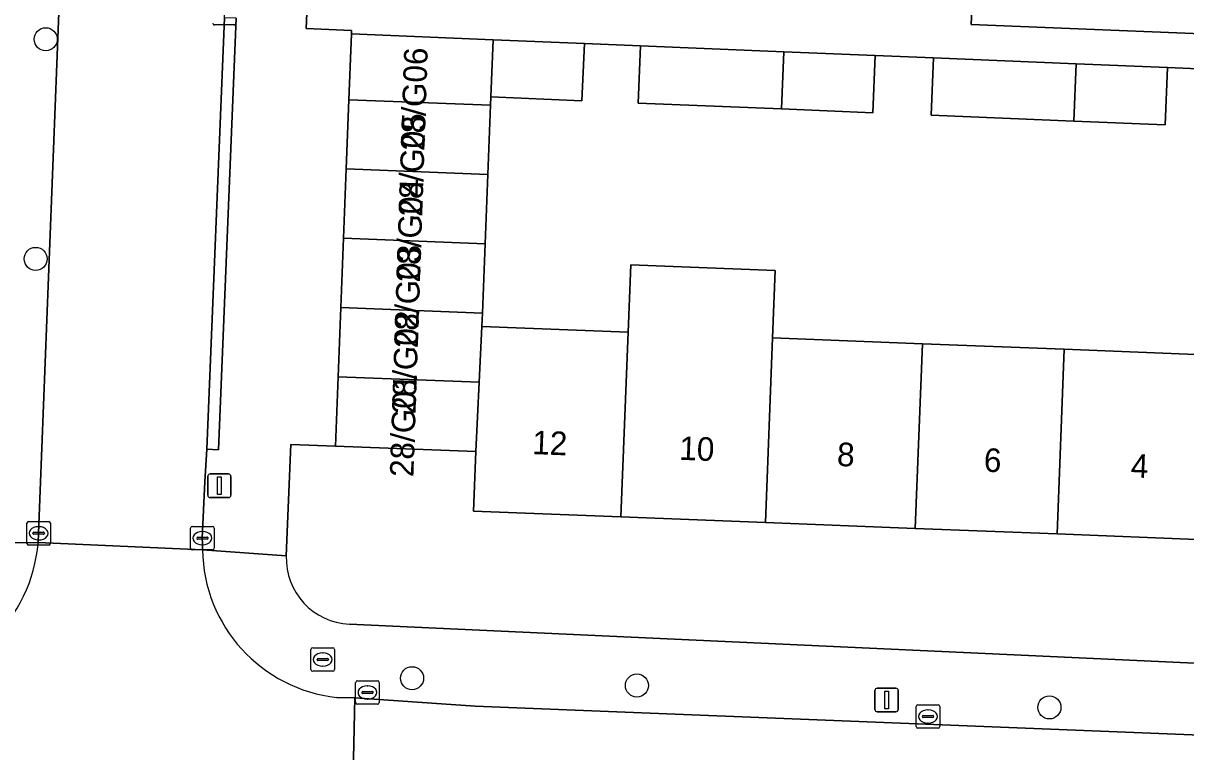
# Model space of a CAD drawing. Extents: x 161354 to 162026, y 386504 to 387460.
# Drawn here: x 161732.92 to 161782.27, y 386817.34 to 386848.27 of the extents above; entities that cross this region are included whole.
import ezdxf

# ---------------------------------------------------------------- set-up
doc = ezdxf.new("R2010")
doc.units = 0
for name, color, linetype in [('IMGEO_Boom', 7, 'Continuous'), ('IMGEO_Brandkraan', 7, 'Continuous'), ('IMGEO_Erf', 7, 'Continuous'), ('IMGEO_Kolk', 7, 'Continuous'), ('IMGEO_Lichtmast', 7, 'Continuous'), ('IMGEO_Pand', 7, 'Continuous'), ('IMGEO_Pand_nummerreeks', 7, 'Continuous'), ('IMGEO_Rijbaan_lokaal_open', 7, 'Continuous'), ('IMGEO_Voetpad_open', 7, 'Continuous')]:
    doc.layers.add(name, color=color, linetype=linetype)

msp = doc.modelspace()

# ---------------------------------------------------------------- linework, layer by layer
at = {"layer": 'IMGEO_Boom'}
for centre in [(161733.871, 386847.589), (161733.442, 386838.265), (161749.424, 386820.465), (161758.968, 386820.154), (161776.484, 386819.225)]:
    msp.add_circle(centre, 0.489, dxfattribs=at)
at = {"layer": 'IMGEO_Brandkraan'}
for p, q in [((161745.131, 386820.831), (161745.131, 386821.683)), ((161745.206, 386821.757), (161746.058, 386821.757)), ((161745.619, 386821.537), (161745.644, 386821.537)), ((161746.132, 386821.683), (161746.132, 386820.831)), ((161745.39, 386821.251), (161745.39, 386821.263)), ((161745.828, 386821.214), (161745.43, 386821.214)), ((161745.433, 386821.3), (161745.831, 386821.3)), ((161745.642, 386820.977), (161745.617, 386820.977)), ((161745.874, 386821.263), (161745.874, 386821.251)), ((161746.058, 386820.757), (161745.206, 386820.757))]:
    msp.add_line(p, q, dxfattribs=at)
for points in [[(161745.131, 386820.831), (161745.131, 386821.683)], [(161745.206, 386821.757), (161746.058, 386821.757)], [(161746.132, 386821.683), (161746.132, 386820.831)], [(161746.058, 386820.757), (161745.206, 386820.757)]]:
    msp.add_lwpolyline(points, dxfattribs=at)
for centre, radius, start, end in [((161745.208, 386821.681), 0.0765, 91.552, 178.448), ((161745.208, 386821.681), 0.0765, 91.552, 178.448), ((161746.056, 386821.681), 0.0765, 1.552, 88.448), ((161746.056, 386821.681), 0.0765, 1.552, 88.448), ((161745.208, 386820.833), 0.0765, 181.552, 268.448), ((161745.208, 386820.833), 0.0765, 181.552, 268.448), ((161745.43, 386821.26), 0.0403, 85.8775, 175.7526), ((161745.427, 386821.25), 0.0366, 178.938, 274.7102), ((161745.831, 386821.257), 0.043, 264.8664, 352.4533), ((161745.835, 386821.262), 0.0386, 1.7309, 96.639), ((161746.056, 386820.833), 0.0765, 271.552, 358.448), ((161746.056, 386820.833), 0.0765, 271.552, 358.448)]:
    msp.add_arc(centre, radius, start, end, dxfattribs=at)
for centre, major_axis, ratio, start_param, end_param in [((161745.618, 386821.257), (-0.387, 0.002), 0.722429, 4.712389, 7.853982), ((161745.643, 386821.257), (-0.39, 0.002), 0.717154, 1.570796, 4.712389)]:
    msp.add_ellipse(centre, major_axis=major_axis, ratio=ratio, start_param=start_param, end_param=end_param, dxfattribs=at)
at = {"layer": 'IMGEO_Erf'}
for points in [[(161774.801, 386890.94), (161774.595, 386885.544), (161776.967, 386885.442), (161776.817, 386881.514), (161776.669, 386877.637), (161774.297, 386877.739), (161774.194, 386875.016), (161774.094, 386872.396), (161776.466, 386872.294), (161776.319, 386868.314), (161776.062, 386861.714), (161773.692, 386861.815), (161773.578, 386858.814), (161775.948, 386858.712), (161775.812, 386855.113), (161775.658, 386851.101), (161773.288, 386851.191), (161773.167, 386848.216), (161787.125, 386847.647)], [(161786.367, 386846.182), (161781.498, 386846.383), (161781.398, 386843.955), (161777.521, 386844.115), (161771.466, 386844.366), (161771.567, 386846.793), (161769.088, 386846.896), (161768.987, 386844.468), (161765.111, 386844.628), (161759.028, 386844.879), (161759.129, 386847.307), (161756.738, 386847.406), (161756.638, 386844.978), (161752.769, 386845.138), (161752.753, 386844.787), (161752.638, 386841.847), (161752.523, 386838.906), (161752.408, 386835.966), (161752.386, 386835.39), (161758.598, 386835.148), (161758.71, 386838.01), (161764.843, 386837.77), (161764.731, 386834.909), (161771.093, 386834.662), (161777.113, 386834.427), (161783.392, 386834.183)], [(161776.807, 386826.59), (161770.787, 386826.824), (161764.425, 386827.072), (161758.292, 386827.311), (161752.029, 386827.555), (161752.128, 386830.087), (161746.171, 386830.319), (161744.271, 386830.386), (161744.084, 386825.658)], [(161796.626, 386823.094), (161796.939, 386828.203), (161795.513, 386828.34), (161795.296, 386828.361), (161789.554, 386828.585), (161789.457, 386826.097), (161783.086, 386826.345), (161776.807, 386826.59)], [(161746.765, 386822.756), (161793.994, 386820.574)]]:
    msp.add_lwpolyline(points, dxfattribs=at)
msp.add_arc((161746.888, 386825.559), 2.805, 177.9708, 267.4955, dxfattribs=at)
at = {"layer": 'IMGEO_Kolk'}
for p, q in [((161741.888, 386848.193), (161741.036, 386848.193)), ((161733.069, 386826.189), (161733.069, 386827.041)), ((161733.144, 386827.115), (161733.996, 386827.115)), ((161733.557, 386826.895), (161733.582, 386826.895)), ((161734.07, 386827.041), (161734.07, 386826.189)), ((161740.023, 386825.982), (161740.023, 386826.834)), ((161740.098, 386826.908), (161740.95, 386826.908)), ((161741.024, 386826.834), (161741.024, 386825.982)), ((161733.328, 386826.609), (161733.328, 386826.621)), ((161733.766, 386826.572), (161733.368, 386826.572)), ((161733.371, 386826.658), (161733.769, 386826.658)), ((161733.58, 386826.335), (161733.555, 386826.335)), ((161733.812, 386826.621), (161733.812, 386826.609)), ((161740.282, 386826.402), (161740.282, 386826.414)), ((161740.72, 386826.365), (161740.322, 386826.365)), ((161740.325, 386826.451), (161740.723, 386826.451)), ((161740.511, 386826.688), (161740.536, 386826.688)), ((161740.766, 386826.414), (161740.766, 386826.402)), ((161733.996, 386826.115), (161733.144, 386826.115)), ((161740.95, 386825.908), (161740.098, 386825.908)), ((161740.534, 386826.128), (161740.509, 386826.128)), ((161747.104, 386820.358), (161747.956, 386820.358)), ((161747.029, 386819.432), (161747.029, 386820.284)), ((161747.288, 386819.852), (161747.288, 386819.864)), ((161747.331, 386819.901), (161747.729, 386819.901)), ((161747.517, 386820.138), (161747.542, 386820.138)), ((161747.772, 386819.864), (161747.772, 386819.852)), ((161748.03, 386820.284), (161748.03, 386819.432)), ((161747.956, 386819.358), (161747.104, 386819.358)), ((161747.726, 386819.815), (161747.328, 386819.815)), ((161747.54, 386819.578), (161747.515, 386819.578)), ((161770.903, 386819.338), (161771.755, 386819.338)), ((161770.828, 386818.412), (161770.828, 386819.264)), ((161771.087, 386818.832), (161771.087, 386818.844)), ((161771.13, 386818.881), (161771.528, 386818.881)), ((161771.316, 386819.118), (161771.341, 386819.118)), ((161771.571, 386818.844), (161771.571, 386818.832)), ((161771.829, 386819.264), (161771.829, 386818.412)), ((161771.525, 386818.795), (161771.127, 386818.795)), ((161771.339, 386818.558), (161771.314, 386818.558)), ((161771.755, 386818.338), (161770.903, 386818.338))]:
    msp.add_line(p, q, dxfattribs=at)
for points in [[(161741.888, 386848.193), (161741.036, 386848.193)], [(161733.069, 386826.189), (161733.069, 386827.041)], [(161733.144, 386827.115), (161733.996, 386827.115)], [(161734.07, 386827.041), (161734.07, 386826.189)], [(161740.023, 386825.982), (161740.023, 386826.834)], [(161740.098, 386826.908), (161740.95, 386826.908)], [(161741.024, 386826.834), (161741.024, 386825.982)], [(161733.996, 386826.115), (161733.144, 386826.115)], [(161740.95, 386825.908), (161740.098, 386825.908)], [(161747.104, 386820.358), (161747.956, 386820.358)], [(161747.029, 386819.432), (161747.029, 386820.284)], [(161748.03, 386820.284), (161748.03, 386819.432)], [(161747.956, 386819.358), (161747.104, 386819.358)], [(161770.903, 386819.338), (161771.755, 386819.338)], [(161770.828, 386818.412), (161770.828, 386819.264)], [(161771.829, 386819.264), (161771.829, 386818.412)], [(161771.755, 386818.338), (161770.903, 386818.338)]]:
    msp.add_lwpolyline(points, dxfattribs=at)
for centre, radius, start, end in [((161741.038, 386848.269), 0.0765, 181.552, 268.448), ((161741.038, 386848.269), 0.0765, 181.552, 268.448), ((161741.886, 386848.269), 0.0765, 271.552, 358.448), ((161741.886, 386848.269), 0.0765, 271.552, 358.448), ((161733.146, 386827.039), 0.0765, 91.552, 178.448), ((161733.146, 386827.039), 0.0765, 91.552, 178.448), ((161733.994, 386827.039), 0.0765, 1.552, 88.448), ((161733.994, 386827.039), 0.0765, 1.552, 88.448), ((161740.1, 386826.832), 0.0765, 91.552, 178.448), ((161740.1, 386826.832), 0.0765, 91.552, 178.448), ((161740.948, 386826.832), 0.0765, 1.552, 88.448), ((161740.948, 386826.832), 0.0765, 1.552, 88.448), ((161733.368, 386826.618), 0.0403, 85.8775, 175.7526), ((161733.365, 386826.608), 0.0366, 178.938, 274.7102), ((161733.769, 386826.615), 0.043, 264.8664, 352.4533), ((161733.773, 386826.62), 0.0386, 1.7309, 96.639), ((161740.322, 386826.411), 0.0403, 85.8775, 175.7526), ((161740.319, 386826.401), 0.0366, 178.938, 274.7102), ((161740.723, 386826.408), 0.043, 264.8664, 352.4533), ((161740.727, 386826.413), 0.0386, 1.7309, 96.639), ((161733.146, 386826.191), 0.0765, 181.552, 268.448), ((161733.146, 386826.191), 0.0765, 181.552, 268.448), ((161733.994, 386826.191), 0.0765, 271.552, 358.448), ((161733.994, 386826.191), 0.0765, 271.552, 358.448), ((161740.1, 386825.984), 0.0765, 181.552, 268.448), ((161740.1, 386825.984), 0.0765, 181.552, 268.448), ((161740.948, 386825.984), 0.0765, 271.552, 358.448), ((161740.948, 386825.984), 0.0765, 271.552, 358.448), ((161747.106, 386820.282), 0.0765, 91.552, 178.448), ((161747.106, 386820.282), 0.0765, 91.552, 178.448), ((161747.954, 386820.282), 0.0765, 1.552, 88.448), ((161747.954, 386820.282), 0.0765, 1.552, 88.448), ((161747.328, 386819.861), 0.0403, 85.8775, 175.7526), ((161747.325, 386819.851), 0.0366, 178.938, 274.7102), ((161747.729, 386819.858), 0.043, 264.8664, 352.4533), ((161747.733, 386819.863), 0.0386, 1.7309, 96.639), ((161747.106, 386819.434), 0.0765, 181.552, 268.448), ((161747.106, 386819.434), 0.0765, 181.552, 268.448), ((161747.954, 386819.434), 0.0765, 271.552, 358.448), ((161747.954, 386819.434), 0.0765, 271.552, 358.448), ((161770.905, 386819.262), 0.0765, 91.552, 178.448), ((161770.905, 386819.262), 0.0765, 91.552, 178.448), ((161771.753, 386819.262), 0.0765, 1.552, 88.448), ((161771.753, 386819.262), 0.0765, 1.552, 88.448), ((161771.127, 386818.841), 0.0403, 85.8775, 175.7526), ((161771.532, 386818.843), 0.0386, 1.7309, 96.639), ((161770.905, 386818.414), 0.0765, 181.552, 268.448), ((161770.905, 386818.414), 0.0765, 181.552, 268.448), ((161771.124, 386818.831), 0.0366, 178.938, 274.7102), ((161771.528, 386818.838), 0.043, 264.8664, 352.4533), ((161771.753, 386818.414), 0.0765, 271.552, 358.448), ((161771.753, 386818.414), 0.0765, 271.552, 358.448)]:
    msp.add_arc(centre, radius, start, end, dxfattribs=at)
for centre, major_axis, ratio, start_param, end_param in [((161733.556, 386826.615), (-0.387, 0.002), 0.722429, 4.712389, 7.853982), ((161733.581, 386826.615), (-0.39, 0.002), 0.717154, 1.570796, 4.712389), ((161740.51, 386826.408), (-0.387, 0.002), 0.722429, 4.712389, 7.853982), ((161740.535, 386826.408), (-0.39, 0.002), 0.717154, 1.570796, 4.712389), ((161747.516, 386819.858), (-0.387, 0.002), 0.722429, 4.712389, 7.853982), ((161747.541, 386819.858), (-0.39, 0.002), 0.717154, 1.570796, 4.712389), ((161771.315, 386818.838), (-0.387, 0.002), 0.722429, 4.712389, 7.853982), ((161771.34, 386818.838), (-0.39, 0.002), 0.717154, 1.570796, 4.712389)]:
    msp.add_ellipse(centre, major_axis=major_axis, ratio=ratio, start_param=start_param, end_param=end_param, dxfattribs=at)
at = {"layer": 'IMGEO_Lichtmast'}
for p, q in [((161740.746, 386828.233), (161740.746, 386829.033)), ((161740.746, 386829.033), (161740.746, 386828.233)), ((161740.846, 386829.133), (161741.636, 386829.133)), ((161741.636, 386829.133), (161740.846, 386829.133)), ((161741.736, 386829.033), (161741.736, 386828.233)), ((161741.736, 386828.233), (161741.736, 386829.033)), ((161741.636, 386828.133), (161740.846, 386828.133)), ((161740.846, 386828.133), (161741.636, 386828.133)), ((161769.077, 386819.141), (161769.077, 386819.941)), ((161769.077, 386819.941), (161769.077, 386819.141)), ((161769.177, 386820.041), (161769.967, 386820.041)), ((161769.967, 386820.041), (161769.177, 386820.041)), ((161770.067, 386819.941), (161770.067, 386819.141)), ((161770.067, 386819.141), (161770.067, 386819.941)), ((161769.967, 386819.041), (161769.177, 386819.041)), ((161769.177, 386819.041), (161769.967, 386819.041))]:
    msp.add_line(p, q, dxfattribs=at)
for points in [[(161741.166, 386829.008), (161741.316, 386829.008), (161741.316, 386828.258), (161741.166, 386828.258), (161741.166, 386829.008)], [(161769.497, 386819.916), (161769.647, 386819.916), (161769.647, 386819.166), (161769.497, 386819.166), (161769.497, 386819.916)]]:
    msp.add_lwpolyline(points, dxfattribs=at)
for centre, start, end in [((161740.846, 386829.033), 90, 180), ((161740.846, 386829.033), 90, 180), ((161741.636, 386829.033), 0, 90), ((161741.636, 386829.033), 360, 90), ((161740.846, 386828.233), 180, 270), ((161740.846, 386828.233), 180, 270), ((161741.636, 386828.233), 270, 0), ((161741.636, 386828.233), 270, 0), ((161769.177, 386819.941), 90, 180), ((161769.177, 386819.941), 90, 180), ((161769.967, 386819.941), 0, 90), ((161769.967, 386819.941), 360, 90), ((161769.177, 386819.141), 180, 270), ((161769.177, 386819.141), 180, 270), ((161769.967, 386819.141), 270, 0), ((161769.967, 386819.141), 270, 0)]:
    msp.add_arc(centre, 0.1, start, end, dxfattribs=at)
at = {"layer": 'IMGEO_Pand'}
for points in [[(161752.862, 386847.566), (161746.853, 386847.815), (161746.744, 386845.022), (161752.753, 386844.787), (161752.769, 386845.138)], [(161756.738, 386847.406), (161752.862, 386847.566), (161752.769, 386845.138), (161756.638, 386844.978)], [(161765.211, 386847.056), (161759.129, 386847.307), (161759.028, 386844.879), (161765.111, 386844.628)], [(161769.088, 386846.896), (161765.211, 386847.056), (161765.111, 386844.628), (161768.987, 386844.468)], [(161777.621, 386846.543), (161771.567, 386846.793), (161771.466, 386844.366), (161777.521, 386844.115)], [(161781.498, 386846.383), (161777.621, 386846.543), (161777.521, 386844.115), (161781.398, 386843.955)], [(161752.638, 386841.847), (161752.753, 386844.787), (161746.744, 386845.022), (161746.63, 386842.081)], [(161746.63, 386842.081), (161746.515, 386839.14), (161752.523, 386838.906), (161752.638, 386841.847)], [(161752.408, 386835.966), (161752.523, 386838.906), (161746.515, 386839.14), (161746.4, 386836.2)], [(161764.731, 386834.909), (161764.843, 386837.77), (161758.71, 386838.01), (161758.598, 386835.148), (161758.292, 386827.311), (161764.425, 386827.072)], [(161746.4, 386836.2), (161746.286, 386833.26), (161752.271, 386833.026), (161752.386, 386835.39), (161752.408, 386835.966)], [(161752.128, 386830.087), (161752.029, 386827.555), (161758.292, 386827.311), (161758.598, 386835.148), (161752.386, 386835.39), (161752.271, 386833.026)], [(161771.093, 386834.662), (161764.731, 386834.909), (161764.425, 386827.072), (161770.787, 386826.824)], [(161770.787, 386826.824), (161776.807, 386826.59), (161777.113, 386834.427), (161771.093, 386834.662)], [(161776.807, 386826.59), (161783.086, 386826.345), (161783.392, 386834.183), (161777.113, 386834.427)], [(161752.128, 386830.087), (161752.271, 386833.026), (161746.286, 386833.26), (161746.171, 386830.319)]]:
    msp.add_lwpolyline(points, close=True, dxfattribs=at)
at = {"layer": 'IMGEO_Rijbaan_lokaal_open'}
msp.add_lwpolyline([(161741.466, 386848.504), (161741.634, 386854.509), (161741.886, 386860.77), (161734.956, 386861.052), (161734.79, 386857.604), (161734.747, 386856.562), (161734.559, 386851.992), (161733.567, 386826.615), (161733.547, 386826.22), (161740.526, 386825.917), (161740.528, 386826.186), (161740.519, 386826.409), (161740.627, 386828.801), (161740.711, 386830.181)], close=True, dxfattribs=at)
for points in [[(161740.526, 386825.917), (161733.547, 386826.22)], [(161745.9, 386812.54), (161746.843, 386812.529), (161746.999, 386819.63)], [(161746.999, 386819.63), (161746.231, 386819.647)], [(161793.525, 386817.619), (161752.101, 386819.28), (161746.999, 386819.63), (161746.843, 386812.529), (161792.228, 386810.766)]]:
    msp.add_lwpolyline(points, dxfattribs=at)
for centre, radius, start, end in [((161727.076, 386826.751), 6.493, 273.0104, 355.3111), ((161746.923, 386826.007), 6.397, 180.8046, 263.7928)]:
    msp.add_arc(centre, radius, start, end, dxfattribs=at)
at = {"layer": 'IMGEO_Voetpad_open'}
for points in [[(161787.125, 386847.647), (161773.167, 386848.216), (161773.288, 386851.191), (161773.441, 386855.215), (161773.578, 386858.814), (161773.692, 386861.815), (161773.943, 386868.416), (161774.094, 386872.396), (161774.194, 386875.016), (161774.297, 386877.739), (161774.445, 386881.616), (161774.595, 386885.544), (161774.801, 386890.94)], [(161730.515, 386826.18), (161733.547, 386826.22), (161733.567, 386826.615), (161734.559, 386851.992), (161734.06, 386852.012), (161734.249, 386856.582), (161734.747, 386856.562), (161734.79, 386857.604), (161734.956, 386861.052), (161735.048, 386863.934), (161735.304, 386870.694), (161736.064, 386886.455)], [(161741.952, 386848.485), (161741.21, 386830.161), (161740.711, 386830.181), (161740.627, 386828.801), (161740.519, 386826.409), (161740.528, 386826.186), (161740.526, 386825.917), (161744.084, 386825.658), (161744.271, 386830.386), (161746.171, 386830.319), (161746.286, 386833.26), (161746.4, 386836.2), (161746.515, 386839.14), (161746.63, 386842.081), (161746.744, 386845.022), (161746.853, 386847.815), (161746.859, 386847.962), (161744.927, 386848.045), (161744.98, 386849.364)], [(161744.98, 386849.364), (161744.927, 386848.045), (161746.859, 386847.962), (161746.853, 386847.815), (161752.862, 386847.566), (161756.738, 386847.406), (161759.129, 386847.307), (161765.211, 386847.056), (161769.088, 386846.896), (161771.567, 386846.793), (161777.621, 386846.543), (161781.498, 386846.383), (161786.367, 386846.182)], [(161733.547, 386826.22), (161730.515, 386826.18)], [(161744.084, 386825.658), (161740.526, 386825.917)], [(161793.994, 386820.574), (161746.765, 386822.756)], [(161746.231, 386819.647), (161746.999, 386819.63), (161752.101, 386819.28), (161793.525, 386817.619)]]:
    msp.add_lwpolyline(points, dxfattribs=at)
msp.add_lwpolyline([(161741.466, 386848.504), (161740.711, 386830.181), (161741.21, 386830.161), (161741.952, 386848.485)], close=True, dxfattribs=at)
for centre, radius, start, end in [((161727.076, 386826.751), 6.493, 273.0104, 355.3111), ((161746.923, 386826.007), 6.397, 180.8046, 263.7928), ((161746.888, 386825.559), 2.805, 177.9708, 267.4955)]:
    msp.add_arc(centre, radius, start, end, dxfattribs=at)

# ---------------------------------------------------------------- texts
at = {"layer": 'IMGEO_Pand_nummerreeks'}
for s, rotation, p in [('28/G06', 88.0751, (161749.945, 386842.836)), ('28/G05', 88.0766, (161749.851, 386840.045)), ('28/G04', 88.0766, (161749.757, 386837.254)), ('28/G03', 88.0766, (161749.664, 386834.462)), ('28/G02', 88.0766, (161749.57, 386831.664)), ('28/G01', 88.0766, (161749.48, 386828.989)), ('12', 357.7692, (161754.509, 386829.98)), ('10', 357.7712, (161760.753, 386829.737)), ('8', 357.7692, (161767.452, 386829.476)), ('6', 357.7692, (161773.686, 386829.233)), ('4', 357.7692, (161779.924, 386828.99))]:
    msp.add_text(s, height=1, rotation=rotation, dxfattribs=at).set_placement(p)

doc.saveas('drawing.dxf')
